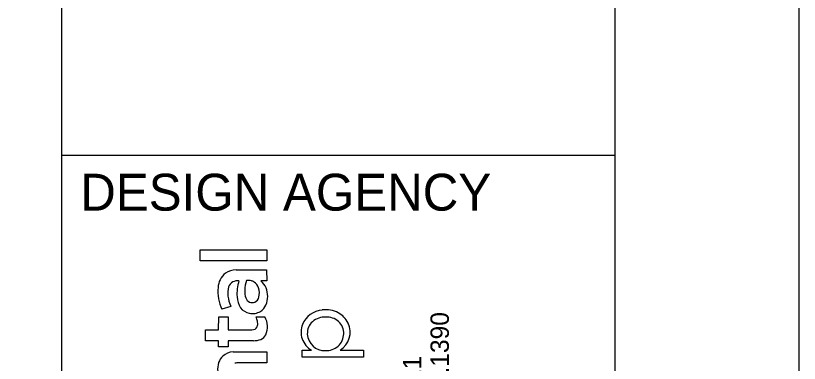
# Model space of a CAD drawing. Extents: x -31.8 to 34, y 0 to 22.
# Drawn here: x 31.875 to 34, y 3.936 to 4.879 of the extents above; entities that cross this region are included whole.
import ezdxf

# ---------------------------------------------------------------- set-up
doc = ezdxf.new("R2010")
doc.units = 0
for name, color, linetype in [('_CIVIL_CONSTRUCTION', 7, 'Continuous'), ('PF_X_Ground_Line', 7, 'Continuous'), ('UT_X_FO', 7, 'Continuous')]:
    doc.layers.add(name, color=color, linetype=linetype)

msp = doc.modelspace()

# ---------------------------------------------------------------- linework, layer by layer
at = {"layer": '_CIVIL_CONSTRUCTION'}
for p, q in [((32.3756, 4.2141), (32.3756, 4.244)), ((32.3756, 4.244), (32.5557, 4.244)), ((32.5557, 4.244), (32.5557, 4.2141)), ((32.5557, 4.2141), (32.3756, 4.2141)), ((32.4727, 4.189), (32.5555, 4.1892)), ((32.5555, 4.1892), (32.5557, 4.1596)), ((32.5557, 4.1596), (32.5397, 4.1596)), ((32.4582, 4.0904), (32.4343, 4.0823)), ((32.4254, 4.027), (32.4255, 4.0621)), ((32.4255, 4.0621), (32.4511, 4.0621)), ((32.4511, 4.0621), (32.4512, 4.027)), ((32.527, 4.0616), (32.5511, 4.0616)), ((32.3896, 3.9972), (32.3896, 4.027)), ((32.3896, 4.027), (32.4254, 4.027)), ((32.4512, 4.027), (32.515, 4.027)), ((32.515, 4.027), (32.52, 4.0275)), ((32.4254, 3.9972), (32.3896, 3.9972)), ((32.4254, 3.9807), (32.4254, 3.9972)), ((32.5197, 3.9972), (32.4511, 3.9972)), ((32.4511, 3.9972), (32.4511, 3.9807)), ((32.4511, 3.9807), (32.4254, 3.9807)), ((32.4644, 3.9669), (32.4729, 3.9673)), ((32.4729, 3.9673), (32.5557, 3.9673)), ((32.5557, 3.9673), (32.5557, 3.9375)), ((32.6515, 3.9521), (32.6515, 3.9711)), ((32.6515, 3.9711), (32.6771, 3.9711)), ((32.7549, 3.9713), (32.8186, 3.9711)), ((32.8186, 3.9711), (32.8184, 3.9521)), ((32.5557, 3.9375), (32.4814, 3.9375)), ((32.8184, 3.9521), (32.6515, 3.9521))]:
    msp.add_line(p, q, dxfattribs=at)
msp.add_lwpolyline([(32.3756, 4.2141), (32.3756, 4.244), (32.5557, 4.244), (32.5557, 4.2141)], close=True, dxfattribs=at)
for points in [[(32.4727, 4.189), (32.5555, 4.1892), (32.5557, 4.1596)], [(32.5557, 4.1596), (32.5397, 4.1596)], [(32.4582, 4.0904), (32.4343, 4.0823)], [(32.5197, 3.9972), (32.4511, 3.9972), (32.4511, 3.9807), (32.4254, 3.9807), (32.4254, 3.9972), (32.3896, 3.9972), (32.3896, 4.027), (32.4254, 4.027), (32.4255, 4.0621), (32.4511, 4.0621), (32.4512, 4.027), (32.515, 4.027), (32.52, 4.0275)], [(32.527, 4.0616), (32.5511, 4.0616)], [(32.4644, 3.9669), (32.4729, 3.9673), (32.5557, 3.9673), (32.5557, 3.9375), (32.4814, 3.9375)], [(32.7549, 3.9713), (32.8186, 3.9711), (32.8184, 3.9521), (32.6515, 3.9521)], [(32.6515, 3.9521), (32.6515, 3.9711), (32.6771, 3.9711)]]:
    msp.add_lwpolyline(points, dxfattribs=at)
for centre, radius, start, end in [((32.4745, 4.1326), 0.0565, 91.8942, 122.6317), ((32.4745, 4.1326), 0.0565, 91.8942, 122.6317), ((32.4685, 4.1447), 0.043, 124.537, 155.6594), ((32.4685, 4.1447), 0.043, 124.537, 155.6594), ((32.4882, 4.1361), 0.0646, 155.9764, 175.3149), ((32.4882, 4.1361), 0.0646, 155.9764, 175.3149), ((32.4753, 4.1356), 0.024, 119.4252, 161.6629), ((32.4753, 4.1356), 0.024, 119.4252, 161.6629), ((32.4779, 4.1278), 0.0321, 85.3802, 116.6222), ((32.4779, 4.1278), 0.0321, 85.3802, 116.6222), ((32.5879, 4.1251), 0.1129, 162.0821, 184.5285), ((32.5879, 4.1251), 0.1129, 162.0821, 184.5285), ((32.5801, 4.1313), 0.0841, 159.8366, 178.0362), ((32.5801, 4.1313), 0.0841, 159.8366, 178.0362), ((32.5051, 4.1074), 0.053, 79.6696, 94.2322), ((32.5051, 4.1074), 0.053, 79.6696, 94.2322), ((32.5089, 4.1364), 0.0238, 56.8913, 76.2149), ((32.5089, 4.1364), 0.0238, 56.8913, 76.2149), ((32.5052, 4.1318), 0.0297, 17.5984, 55.7282), ((32.5052, 4.1318), 0.0297, 17.5984, 55.7282), ((32.5055, 4.1191), 0.0529, 358.0746, 49.762), ((32.5055, 4.1191), 0.0529, 358.0746, 49.762), ((32.5364, 4.1308), 0.113, 174.6101, 205.3899), ((32.5364, 4.1308), 0.113, 174.6101, 205.3899), ((32.5076, 4.1265), 0.0576, 163.1369, 188.1675), ((32.5076, 4.1265), 0.0576, 163.1369, 188.1675), ((32.5466, 4.1303), 0.0506, 175.5903, 199.8857), ((32.5466, 4.1303), 0.0506, 175.5903, 199.8857), ((32.4916, 4.1264), 0.0443, 345.9408, 18.9919), ((32.4916, 4.1264), 0.0443, 345.9408, 18.9919), ((32.5473, 4.1297), 0.0973, 186.7598, 203.7981), ((32.5473, 4.1297), 0.0973, 186.7598, 203.7981), ((32.5328, 4.1187), 0.0575, 182.5676, 213.7144), ((32.5328, 4.1187), 0.0575, 182.5676, 213.7144), ((32.5164, 4.1189), 0.0184, 198.2844, 293.3081), ((32.5164, 4.1189), 0.0184, 198.2844, 293.3081), ((32.5152, 4.1199), 0.0199, 295.2883, 347.4639), ((32.5152, 4.1199), 0.0199, 295.2883, 347.4639), ((32.5019, 4.1168), 0.0566, 336.016, 0.5951), ((32.5019, 4.1168), 0.0566, 336.016, 0.5951), ((32.5149, 4.1078), 0.0366, 215.0668, 259.8133), ((32.5149, 4.1078), 0.0366, 215.0668, 259.8133), ((32.5175, 4.1097), 0.0394, 303.4436, 336.18), ((32.5175, 4.1097), 0.0394, 303.4436, 336.18), ((32.7108, 4.0182), 0.0624, 93.9866, 158.3119), ((32.7108, 4.0182), 0.0624, 93.9866, 158.3119), ((32.7156, 4.0065), 0.0746, 62.6889, 97.0135), ((32.7156, 4.0065), 0.0746, 62.6889, 97.0135), ((32.5175, 4.1131), 0.0423, 257.5256, 300.882), ((32.5175, 4.1131), 0.0423, 257.5256, 300.882), ((32.4863, 4.042), 0.0452, 10.1545, 25.723), ((32.4863, 4.042), 0.0452, 10.1545, 25.723), ((32.503, 4.0351), 0.0549, 336.589, 28.8991), ((32.503, 4.0351), 0.0549, 336.589, 28.8991), ((32.7138, 4.0102), 0.0513, 87.8965, 131.1812), ((32.7138, 4.0102), 0.0513, 87.8965, 131.1812), ((32.7175, 4.0102), 0.0513, 49.9089, 92.0363), ((32.7175, 4.0102), 0.0513, 49.9089, 92.0363), ((32.7212, 4.0191), 0.0608, 25.0657, 61.9602), ((32.7212, 4.0191), 0.0608, 25.0657, 61.9602), ((32.5184, 4.04), 0.0126, 277.6142, 353.7918), ((32.5184, 4.04), 0.0126, 277.6142, 353.7918), ((32.4957, 4.0436), 0.0356, 351.914, 10.2059), ((32.4957, 4.0436), 0.0356, 351.914, 10.2059), ((32.707, 4.0202), 0.0581, 158.656, 198.171), ((32.707, 4.0202), 0.0581, 158.656, 198.171), ((32.7092, 4.0167), 0.0434, 132.3289, 182.0949), ((32.7092, 4.0167), 0.0434, 132.3289, 182.0949), ((32.7215, 4.0173), 0.0433, 358.0487, 47.9447), ((32.7215, 4.0173), 0.0433, 358.0487, 47.9447), ((32.7245, 4.02), 0.0574, 301.9776, 25.6418), ((32.7245, 4.02), 0.0574, 301.9776, 25.6418), ((32.5209, 4.0486), 0.0514, 268.6727, 291.5235), ((32.5209, 4.0486), 0.0514, 268.6727, 291.5235), ((32.5291, 4.0261), 0.0275, 292.6889, 332.0598), ((32.5291, 4.0261), 0.0275, 292.6889, 332.0598), ((32.7103, 4.0243), 0.0627, 200.8399, 238.0162), ((32.7103, 4.0243), 0.0627, 200.8399, 238.0162), ((32.7135, 4.0181), 0.0478, 183.5974, 271.7045), ((32.7135, 4.0181), 0.0478, 183.5974, 271.7045), ((32.7172, 4.018), 0.0477, 267.3149, 357.4019), ((32.7172, 4.018), 0.0477, 267.3149, 357.4019), ((32.4635, 3.9255), 0.0402, 132.2238, 161.6823), ((32.4635, 3.9255), 0.0402, 132.2238, 161.6823), ((32.4687, 3.9172), 0.0499, 94.9706, 130.2248), ((32.4687, 3.9172), 0.0499, 94.9706, 130.2248), ((32.4787, 3.9211), 0.056, 162.274, 187.7917), ((32.4787, 3.9211), 0.056, 162.274, 187.7917), ((32.4811, 3.8915), 0.046, 89.6051, 105.3303), ((32.4811, 3.8915), 0.046, 89.6051, 105.3303)]:
    msp.add_arc(centre, radius, start, end, dxfattribs=at)
at = {"layer": 'PF_X_Ground_Line'}
for p, q in [((32, 0.5), (32, 21.5)), ((32, 4.5), (33.5, 4.5))]:
    msp.add_line(p, q, dxfattribs=at)
msp.add_lwpolyline([(1.5, 21.5), (33.5, 21.5), (33.5, 0.5), (1.5, 0.5)], close=True, dxfattribs=at)
at = {"layer": 'UT_X_FO'}
msp.add_lwpolyline([(0, 0), (34, 0), (34, 22), (0, 22)], close=True, dxfattribs=at)

# ---------------------------------------------------------------- texts
at = {"layer": '_CIVIL_CONSTRUCTION'}
msp.add_text('DESIGN AGENCY', height=0.1, dxfattribs=at).set_placement((32.05, 4.35))
for s, p in [('800.835.1390', (33.0497, 3.6671)), ('450 GRANT ST., AKRON, OH  44311', (32.9749, 2.8374))]:
    msp.add_text(s, height=0.049846, rotation=90, dxfattribs=at).set_placement(p)

doc.saveas('drawing.dxf')
